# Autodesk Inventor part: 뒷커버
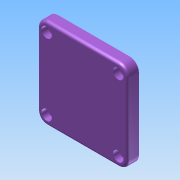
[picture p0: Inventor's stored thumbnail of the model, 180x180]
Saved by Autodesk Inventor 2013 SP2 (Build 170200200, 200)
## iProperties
Created: 2025-06
Part Number: 뒷커버
Material: Generic
Document SubType Name: Modeling
Designer: a
Density: 1 g/cm^3
Author: a
변환 표준: STEP AP214IS
전처리기: Build: 200, Release: 2013 SP2 Update 6 - Date: Thu 07/17/2014
전송 단위: 밀리미터
불확실성: 0.01
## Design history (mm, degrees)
node "뒷커버1"
node "솔리드1"
node "기준1"
